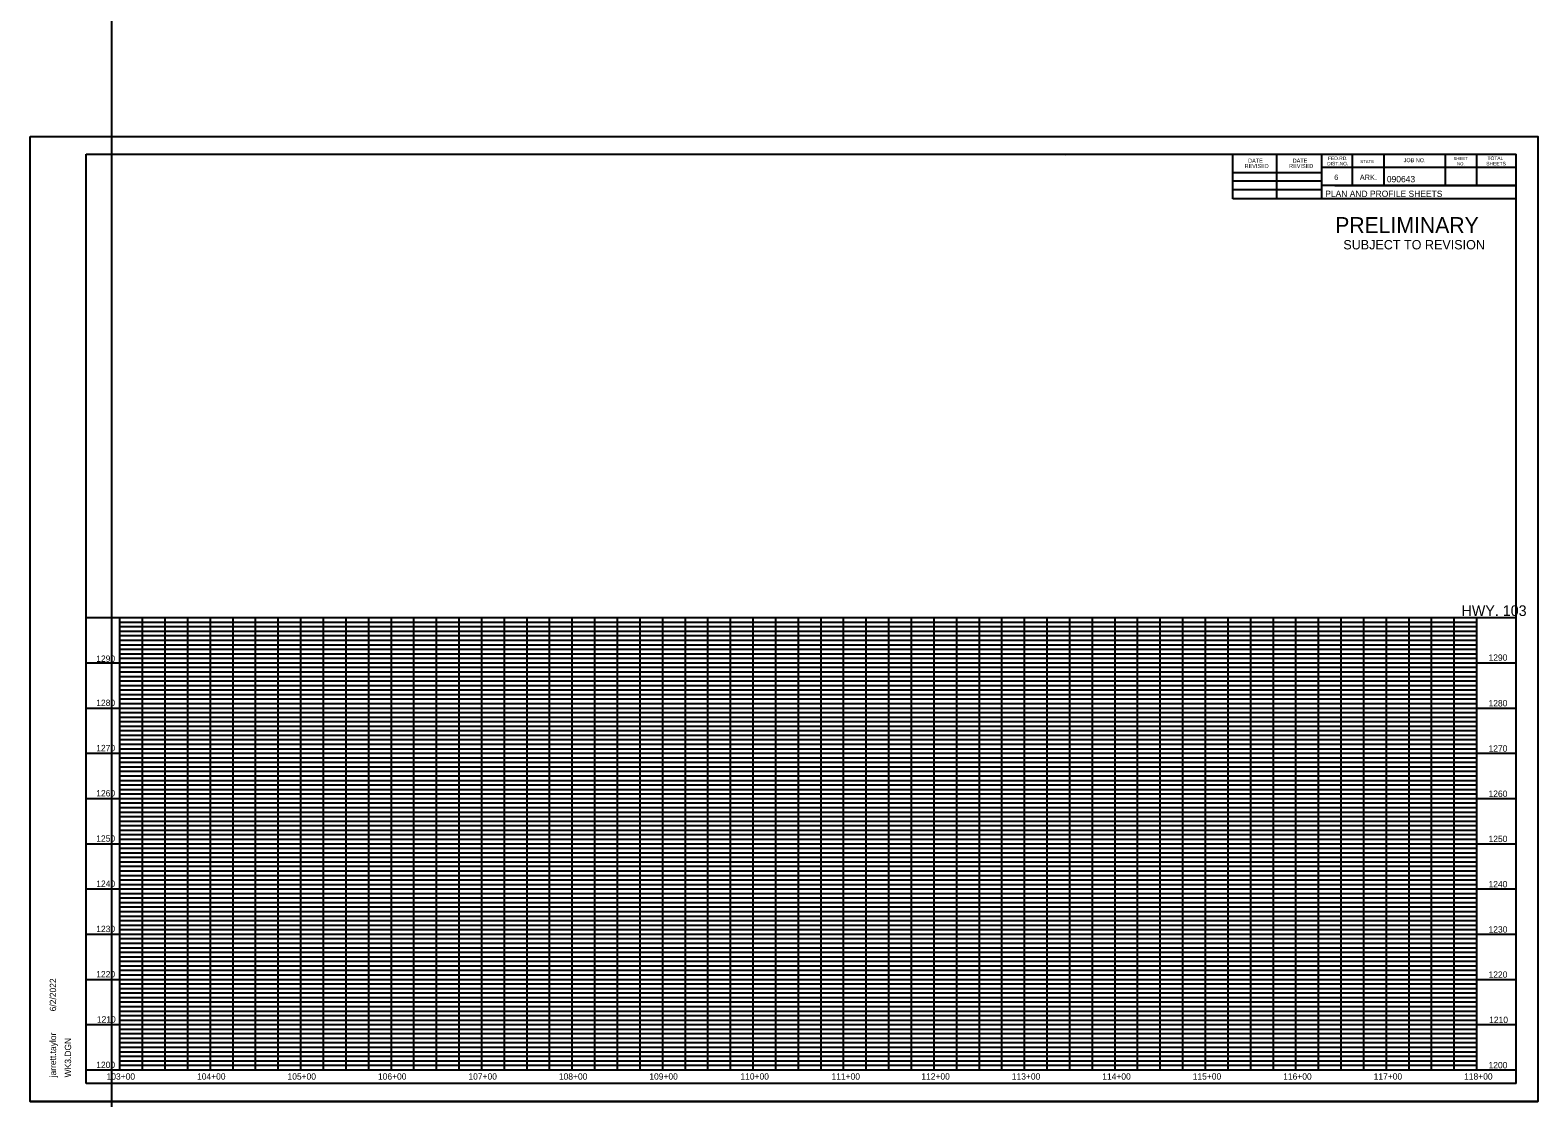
# Model space of a CAD drawing. Extents: x 1386057 to 1388056, y 1972278 to 1974778.
# Drawn here: x 1386066 to 1387733, y 1972278 to 1973468 of the extents above; entities that cross this region are included whole.
import ezdxf

# ---------------------------------------------------------------- set-up
doc = ezdxf.new("R2010")
doc.units = 0
for name, color, linetype in [('Default', 7, 'Continuous'), ('PROFILE_CELL', 7, 'Continuous'), ('R_Border', 7, 'Continuous'), ('R_Border Prem', 7, 'Continuous'), ('R_Grid', 7, 'Continuous'), ('R_No Plot', 7, 'Continuous')]:
    doc.layers.add(name, color=color, linetype=linetype)

msp = doc.modelspace()

# ---------------------------------------------------------------- linework, layer by layer
at = {"layer": 'PROFILE_CELL'}
msp.add_line((1386156.5, 1973527.8), (1386156.5, 1972277.8), dxfattribs=at)
at = {"layer": 'R_Border'}
for p, q in [((1386128.4, 1973331), (1387709.3, 1973331)), ((1386128.4, 1972303.7), (1386128.4, 1973331)), ((1387210.5, 1973329.7), (1387210.5, 1973329.7)), ((1387210.5, 1973329.7), (1387210.5, 1973329.7)), ((1387396.1, 1973281.6), (1387396.1, 1973331)), ((1387444.5, 1973281.6), (1387444.5, 1973331)), ((1387493.8, 1973331), (1387493.8, 1973281.6)), ((1387528, 1973331), (1387528, 1973296.3)), ((1387562.7, 1973331), (1387562.7, 1973296.3)), ((1387630.6, 1973331), (1387630.6, 1973296.3)), ((1387665.3, 1973331), (1387665.3, 1973296.3)), ((1387709.3, 1972303.7), (1387709.3, 1973331)), ((1387396.1, 1973310.9), (1387493.8, 1973310.9)), ((1387709.3, 1973316.3), (1387493.8, 1973316.3)), ((1387396.1, 1973301.6), (1387493.8, 1973301.6)), ((1387396.1, 1973291.9), (1387493.8, 1973291.9)), ((1387709.3, 1973296.3), (1387493.8, 1973296.3)), ((1387508.6, 1973296.3), (1387709.3, 1973296.3)), ((1387709.3, 1973281.6), (1387396.1, 1973281.6)), ((1387709.3, 1972818.4), (1386128.4, 1972818.4)), ((1386165.7, 1972318.4), (1386165.7, 1972818.4)), ((1386215.7, 1972318.4), (1386215.7, 1972818.4)), ((1386265.7, 1972318.4), (1386265.7, 1972818.4)), ((1386315.7, 1972318.4), (1386315.7, 1972818.4)), ((1386365.7, 1972318.4), (1386365.7, 1972818.4)), ((1386415.7, 1972318.4), (1386415.7, 1972818.4)), ((1386465.7, 1972318.4), (1386465.7, 1972818.4)), ((1386515.7, 1972318.4), (1386515.7, 1972818.4)), ((1386565.7, 1972318.4), (1386565.7, 1972818.4)), ((1386615.7, 1972318.4), (1386615.7, 1972818.4)), ((1386665.7, 1972318.4), (1386665.7, 1972818.4)), ((1386715.7, 1972318.4), (1386715.7, 1972818.4)), ((1386765.7, 1972318.4), (1386765.7, 1972818.4)), ((1386815.7, 1972318.4), (1386815.7, 1972818.4)), ((1386865.7, 1972318.4), (1386865.7, 1972818.4)), ((1386915.7, 1972318.4), (1386915.7, 1972818.4)), ((1386965.7, 1972318.4), (1386965.7, 1972818.4)), ((1387015.7, 1972318.4), (1387015.7, 1972818.4)), ((1387065.7, 1972318.4), (1387065.7, 1972818.4)), ((1387115.7, 1972318.4), (1387115.7, 1972818.4)), ((1387165.7, 1972318.4), (1387165.7, 1972818.4)), ((1387215.7, 1972318.4), (1387215.7, 1972818.4)), ((1387265.7, 1972318.4), (1387265.7, 1972818.4)), ((1387315.7, 1972318.4), (1387315.7, 1972818.4)), ((1387365.7, 1972318.4), (1387365.7, 1972818.4)), ((1387415.7, 1972318.4), (1387415.7, 1972818.4)), ((1387465.7, 1972318.4), (1387465.7, 1972818.4)), ((1387515.7, 1972318.4), (1387515.7, 1972818.4)), ((1387565.7, 1972318.4), (1387565.7, 1972818.4)), ((1387615.7, 1972318.4), (1387615.7, 1972818.4)), ((1387665.7, 1972318.4), (1387665.7, 1972818.4)), ((1387709.3, 1972768.4), (1386128.4, 1972768.4)), ((1387709.3, 1972718.4), (1386128.4, 1972718.4)), ((1387709.3, 1972668.4), (1386128.4, 1972668.4)), ((1387709.3, 1972618.4), (1386128.4, 1972618.4)), ((1387709.3, 1972568.4), (1386128.4, 1972568.4)), ((1387709.3, 1972518.4), (1386128.4, 1972518.4)), ((1387709.3, 1972468.4), (1386128.4, 1972468.4)), ((1387709.3, 1972418.4), (1386128.4, 1972418.4)), ((1387709.3, 1972368.4), (1386128.4, 1972368.4)), ((1387709.3, 1972318.4), (1386128.4, 1972318.4)), ((1386128.4, 1972303.7), (1386128.4, 1972303.7)), ((1387709.3, 1972303.7), (1386128.4, 1972303.7))]:
    msp.add_line(p, q, dxfattribs=at)
at = {"layer": 'R_Grid'}
for p, q in [((1387665.7, 1972813.4), (1386165.7, 1972813.4)), ((1387665.7, 1972808.4), (1386165.7, 1972808.4)), ((1386190.7, 1972318.4), (1386190.7, 1972818.4)), ((1386240.7, 1972318.4), (1386240.7, 1972818.4)), ((1386290.7, 1972318.4), (1386290.7, 1972818.4)), ((1386340.7, 1972318.4), (1386340.7, 1972818.4)), ((1386390.7, 1972318.4), (1386390.7, 1972818.4)), ((1386440.7, 1972318.4), (1386440.7, 1972818.4)), ((1386490.7, 1972318.4), (1386490.7, 1972818.4)), ((1386540.7, 1972318.4), (1386540.7, 1972818.4)), ((1386590.7, 1972318.4), (1386590.7, 1972818.4)), ((1386640.7, 1972318.4), (1386640.7, 1972818.4)), ((1386690.7, 1972318.4), (1386690.7, 1972818.4)), ((1386740.7, 1972318.4), (1386740.7, 1972818.4)), ((1386790.7, 1972318.4), (1386790.7, 1972818.4)), ((1386840.7, 1972318.4), (1386840.7, 1972818.4)), ((1386890.7, 1972318.4), (1386890.7, 1972818.4)), ((1386940.7, 1972318.4), (1386940.7, 1972818.4)), ((1386990.7, 1972318.4), (1386990.7, 1972818.4)), ((1387040.7, 1972318.4), (1387040.7, 1972818.4)), ((1387090.7, 1972318.4), (1387090.7, 1972818.4)), ((1387140.7, 1972318.4), (1387140.7, 1972818.4)), ((1387190.7, 1972318.4), (1387190.7, 1972818.4)), ((1387240.7, 1972318.4), (1387240.7, 1972818.4)), ((1387290.7, 1972318.4), (1387290.7, 1972818.4)), ((1387340.7, 1972318.4), (1387340.7, 1972818.4)), ((1387390.7, 1972318.4), (1387390.7, 1972818.4)), ((1387440.7, 1972318.4), (1387440.7, 1972818.4)), ((1387490.7, 1972318.4), (1387490.7, 1972818.4)), ((1387540.7, 1972318.4), (1387540.7, 1972818.4)), ((1387590.7, 1972318.4), (1387590.7, 1972818.4)), ((1387640.7, 1972318.4), (1387640.7, 1972818.4)), ((1387665.7, 1972803.4), (1386165.7, 1972803.4)), ((1387665.7, 1972798.4), (1386165.7, 1972798.4)), ((1387665.7, 1972793.4), (1386165.7, 1972793.4)), ((1387665.7, 1972788.4), (1386165.7, 1972788.4)), ((1387665.7, 1972783.4), (1386165.7, 1972783.4)), ((1387665.7, 1972778.4), (1386165.7, 1972778.4)), ((1387665.7, 1972773.4), (1386165.7, 1972773.4)), ((1387665.7, 1972763.4), (1386165.7, 1972763.4)), ((1387665.7, 1972758.4), (1386165.7, 1972758.4)), ((1387665.7, 1972753.4), (1386165.7, 1972753.4)), ((1387665.7, 1972748.4), (1386165.7, 1972748.4)), ((1387665.7, 1972743.4), (1386165.7, 1972743.4)), ((1387665.7, 1972738.4), (1386165.7, 1972738.4)), ((1387665.7, 1972733.4), (1386165.7, 1972733.4)), ((1387665.7, 1972728.4), (1386165.7, 1972728.4)), ((1387665.7, 1972723.4), (1386165.7, 1972723.4)), ((1387665.7, 1972713.4), (1386165.7, 1972713.4)), ((1387665.7, 1972708.4), (1386165.7, 1972708.4)), ((1387665.7, 1972703.4), (1386165.7, 1972703.4)), ((1387665.7, 1972698.4), (1386165.7, 1972698.4)), ((1387665.7, 1972693.4), (1386165.7, 1972693.4)), ((1387665.7, 1972688.4), (1386165.7, 1972688.4)), ((1387665.7, 1972683.4), (1386165.7, 1972683.4)), ((1387665.7, 1972678.4), (1386165.7, 1972678.4)), ((1387665.7, 1972673.4), (1386165.7, 1972673.4)), ((1387665.7, 1972663.4), (1386165.7, 1972663.4)), ((1387665.7, 1972658.4), (1386165.7, 1972658.4)), ((1387665.7, 1972653.4), (1386165.7, 1972653.4)), ((1387665.7, 1972648.4), (1386165.7, 1972648.4)), ((1387665.7, 1972643.4), (1386165.7, 1972643.4)), ((1387665.7, 1972638.4), (1386165.7, 1972638.4)), ((1387665.7, 1972633.4), (1386165.7, 1972633.4)), ((1387665.7, 1972628.4), (1386165.7, 1972628.4)), ((1387665.7, 1972623.4), (1386165.7, 1972623.4)), ((1387665.7, 1972613.4), (1386165.7, 1972613.4)), ((1387665.7, 1972608.4), (1386165.7, 1972608.4)), ((1387665.7, 1972603.4), (1386165.7, 1972603.4)), ((1387665.7, 1972598.4), (1386165.7, 1972598.4)), ((1387665.7, 1972593.4), (1386165.7, 1972593.4)), ((1387665.7, 1972588.4), (1386165.7, 1972588.4)), ((1387665.7, 1972583.4), (1386165.7, 1972583.4)), ((1387665.7, 1972578.4), (1386165.7, 1972578.4)), ((1387665.7, 1972573.4), (1386165.7, 1972573.4)), ((1387665.7, 1972563.4), (1386165.7, 1972563.4)), ((1387665.7, 1972558.4), (1386165.7, 1972558.4)), ((1387665.7, 1972553.4), (1386165.7, 1972553.4)), ((1387665.7, 1972548.4), (1386165.7, 1972548.4)), ((1387665.7, 1972543.4), (1386165.7, 1972543.4)), ((1387665.7, 1972538.4), (1386165.7, 1972538.4)), ((1387665.7, 1972533.4), (1386165.7, 1972533.4)), ((1387665.7, 1972528.4), (1386165.7, 1972528.4)), ((1387665.7, 1972523.4), (1386165.7, 1972523.4)), ((1387665.7, 1972513.4), (1386165.7, 1972513.4)), ((1387665.7, 1972508.4), (1386165.7, 1972508.4)), ((1387665.7, 1972503.4), (1386165.7, 1972503.4)), ((1387665.7, 1972498.4), (1386165.7, 1972498.4)), ((1387665.7, 1972493.4), (1386165.7, 1972493.4)), ((1387665.7, 1972488.4), (1386165.7, 1972488.4)), ((1387665.7, 1972483.4), (1386165.7, 1972483.4)), ((1387665.7, 1972478.4), (1386165.7, 1972478.4)), ((1387665.7, 1972473.4), (1386165.7, 1972473.4)), ((1387665.7, 1972463.4), (1386165.7, 1972463.4)), ((1387665.7, 1972458.4), (1386165.7, 1972458.4)), ((1387665.7, 1972453.4), (1386165.7, 1972453.4)), ((1387665.7, 1972448.4), (1386165.7, 1972448.4)), ((1387665.7, 1972443.4), (1386165.7, 1972443.4)), ((1387665.7, 1972438.4), (1386165.7, 1972438.4)), ((1387665.7, 1972433.4), (1386165.7, 1972433.4)), ((1387665.7, 1972428.4), (1386165.7, 1972428.4)), ((1387665.7, 1972423.4), (1386165.7, 1972423.4)), ((1387665.7, 1972413.4), (1386165.7, 1972413.4)), ((1387665.7, 1972408.4), (1386165.7, 1972408.4)), ((1387665.7, 1972403.4), (1386165.7, 1972403.4)), ((1387665.7, 1972398.4), (1386165.7, 1972398.4)), ((1387665.7, 1972393.4), (1386165.7, 1972393.4)), ((1387665.7, 1972388.4), (1386165.7, 1972388.4)), ((1387665.7, 1972383.4), (1386165.7, 1972383.4)), ((1387665.7, 1972378.4), (1386165.7, 1972378.4)), ((1387665.7, 1972373.4), (1386165.7, 1972373.4)), ((1387665.7, 1972363.4), (1386165.7, 1972363.4)), ((1387665.7, 1972358.4), (1386165.7, 1972358.4)), ((1387665.7, 1972353.4), (1386165.7, 1972353.4)), ((1387665.7, 1972348.4), (1386165.7, 1972348.4)), ((1387665.7, 1972343.4), (1386165.7, 1972343.4)), ((1387665.7, 1972338.4), (1386165.7, 1972338.4)), ((1387665.7, 1972333.4), (1386165.7, 1972333.4)), ((1387665.7, 1972328.4), (1386165.7, 1972328.4)), ((1387665.7, 1972323.4), (1386165.7, 1972323.4))]:
    msp.add_line(p, q, dxfattribs=at)
at = {"layer": 'R_No Plot'}
for p, q in [((1386066.4, 1973350.5), (1387733.1, 1973350.5)), ((1386066.4, 1972283.8), (1387733.1, 1972283.8))]:
    msp.add_line(p, q, dxfattribs=at)
msp.add_lwpolyline([(1386066.4, 1973350.5), (1387733.1, 1973350.5), (1387733.1, 1972283.8), (1386066.4, 1972283.8)], close=True, dxfattribs=at)

# ---------------------------------------------------------------- texts
at = {"layer": 'Default'}
for s, p in [('1290', (1386139.5, 1972769.8)), ('1290', (1387678.6, 1972771)), ('1280', (1386139.5, 1972721)), ('1280', (1387678.6, 1972720.5)), ('1270', (1386139.5, 1972671)), ('1270', (1387678.6, 1972670.5)), ('1260', (1386139.5, 1972621)), ('1260', (1387678.6, 1972620.5)), ('1250', (1386139.5, 1972571)), ('1250', (1387678.6, 1972570.5)), ('1240', (1386139.5, 1972521)), ('1240', (1387678.6, 1972520.5)), ('1230', (1386139.5, 1972471)), ('1230', (1387678.6, 1972470.5)), ('1220', (1386139.5, 1972421)), ('1220', (1387678.6, 1972420.5)), ('1210', (1386140.2, 1972371)), ('1210', (1387679.3, 1972370.5)), ('1200', (1386139.5, 1972320.7)), ('1200', (1387678.6, 1972320.4)), ('103+00', (1386150.9, 1972307.9)), ('104+00', (1386250.9, 1972307.9)), ('105+00', (1386350.9, 1972307.9)), ('106+00', (1386450.9, 1972307.9)), ('107+00', (1386550.9, 1972307.9)), ('108+00', (1386650.9, 1972307.9)), ('109+00', (1386750.9, 1972307.9)), ('110+00', (1386851.6, 1972307.9)), ('111+00', (1386952.3, 1972307.9)), ('112+00', (1387051.6, 1972307.9)), ('113+00', (1387151.6, 1972307.9)), ('114+00', (1387251.6, 1972307.9)), ('115+00', (1387351.6, 1972307.9)), ('116+00', (1387451.6, 1972307.9)), ('117+00', (1387551.6, 1972307.9)), ('118+00', (1387651.6, 1972307.9))]:
    msp.add_text(s, height=7, dxfattribs=at).set_placement(p)
at = {"layer": 'R_Border'}
for s, height, p in [('DATE', 4.4, (1387412.8, 1973321.7)), ('DATE', 4.4, (1387462.1, 1973321.7)), ('FED.RD.', 3.91, (1387501.2, 1973324.6)), ('STATE', 3.42, (1387536.8, 1973321.2)), ('JOB NO.', 4.4, (1387584.7, 1973322.2)), ('SHEET', 3.42, (1387639.9, 1973324.6)), ('TOTAL', 3.91, (1387677.5, 1973324.6)), ('REVISED', 4.4, (1387408.9, 1973315.8)), ('REVISED', 4.4, (1387458.2, 1973315.8)), ('DIST.NO.', 3.91, (1387500.2, 1973318.7)), ('6', 5.86, (1387508, 1973302.6)), ('ARK.', 5.86, (1387536.3, 1973302.6)), ('090643', 7, (1387566.2, 1973300)), ('NO.', 3.42, (1387643.8, 1973318.7)), ('SHEETS', 3.91, (1387676.1, 1973318.7)), ('PLAN AND PROFILE SHEETS', 7, (1387498.1, 1973283.8)), ('HWY. 103', 11.79, (1387648.8, 1972820.5))]:
    msp.add_text(s, height=height, dxfattribs=at).set_placement(p)
for s, p in [('6/2/2022', (1386095.1, 1972383.4)), ('jarrett.taylor', (1386095.1, 1972310.4)), ('WK3.DGN', (1386111.7, 1972310.4))]:
    msp.add_text(s, height=7, rotation=90, dxfattribs=at).set_placement(p)
at = {"layer": 'R_Border Prem'}
for s, height, p in [('PRELIMINARY', 17.5, (1387509.1, 1973244)), ('SUBJECT TO REVISION', 10.376, (1387518.1, 1973225.8))]:
    msp.add_text(s, height=height, dxfattribs=at).set_placement(p)

doc.saveas('drawing.dxf')
